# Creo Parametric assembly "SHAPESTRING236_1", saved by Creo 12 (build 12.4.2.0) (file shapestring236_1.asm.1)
Units: Custom; MM, KILOGRAM, SECS

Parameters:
  PTC_WM_ITERATION = "0"
  PTC_WM_VERSION = "-.0"
  PTC_WM_LIFECYCLE_STATE = "In Work"
  PTC_WM_LIFECYCLE = "MO_CADDocument"
  PTC_WM_CREATED_BY = "Maximilian Roepper (Z0017RMS: MO)"
  PTC_WM_CREATED_ON = "18-Sep-26 11:36:42 AM"
  PTC_WM_MODIFIED_BY = "Maximilian Roepper (Z0017RMS: MO)"
  PTC_WM_MODIFIED_ON = "18-Sep-26 11:36:46 AM"
  PDMLINKNUMBER = "PDM000071455300"
  PTC_WM_NAME = "shapestring236_1.asm"
  PTC_WM_NUMBER = "PDM000071455300"

Other parameters: WEIGHT, WEIGHT_FACTOR, WEIGHT_ADD, MC_ERRORS, SUPPLIER, ISPOSITIONINGASSEMBLY

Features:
  1. coordinate system
  2. imported feature
  3. component "SHAPESTRING093_1"
  4. component "SHAPESTRING235_1"

Other named items: DRW_VIEW_ORG, ROUGH-GROB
